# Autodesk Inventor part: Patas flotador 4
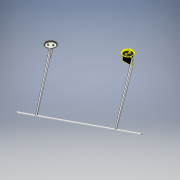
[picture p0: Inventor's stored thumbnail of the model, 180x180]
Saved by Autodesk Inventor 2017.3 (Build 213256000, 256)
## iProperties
Part Number: Patas flotador 4
Material: Plástico ABS
Document SubType Name: Modeling
Designer: PABLO HERNANDEZ
Density: 1.06 g/cm^3
Appearance: Suave - Blanco
Mass: 4.28877 g
Surface Area: 39.5254 cm^2
Volume: 4.04601 cm^3
Author: M.RICO
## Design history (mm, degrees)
sketch "Boceto1"
  geometry: C1 r 16 at (0, 0); 1 further point
  constraints: 1 centre point, 1 coincident
  dimensions: "d0" = 32 diameter of C1
extrude "Extrusión1" new body sketch "Boceto1" distance "d1" = 1; taper "d2" = 0 deg; dims "d93" = 1, "d94" = 0
sketch "Boceto2"
  geometry: C1 r 16 at (0, 0); C2 r 15 at (0, 0); C3 r 14 at (0, 0); 1 further point
  constraints: 3 centre point, 1 coincident
  dimensions: "d3" = 1 radial gap between concentric circles of C1 C2; "d4" = 1 radial gap between concentric circles of C2 C3
extrude "Extrusión2" join sketch "Boceto2" distance "d5" = 3; taper "d6" = 0 deg
sketch "Boceto3"
  geometry: C1 r 15 at (0, 0); C2 r 14 at (0, 0); 1 further point
  constraints: 2 centre point, 1 coincident
  dimensions: "d7" = 1 radial gap between concentric circles of C1 C2; "d123" = 30 diameter of C1
extrude "Extrusión3" join sketch "Boceto3" distance "d8" = 2; taper "d9" = 0 deg
sketch "Boceto4"
  geometry: C1 r 16 at (0, 0); 1 further point
  constraints: 1 centre point, 1 coincident
extrude "Extrusión4" cut sketch "Boceto4" distance "d10" = 0.5; taper "d11" = 0 deg
sketch "Boceto7"
  geometry: L1 (1.5, -15.93)-(1.5, 15.93); L2 (-1.5, -15.93)-(-1.5, 15.93); A1 r 16 centre (0, 0) between (1.5, 15.93) and (-1.5, 15.93); A2 r 16 centre (0, 0) between (-1.5, -15.93) and (1.5, -15.93); 2 further points
  constraints: 4 end point, 4 point on circle, 2 centre point, 1 coincident
extrude "Extrusión7" join sketch "Boceto7" distance "d63" = 25; taper "d64" = 0 deg
fillet "Empalme2" dims "d95" = 3
fillet "Empalme3" dims "d96" = 0.5
sketch "Boceto13"
  geometry: C1 r 1.2 at (-6, 0) reference; C2 r 1.75 at (-6, 0); C3 r 1.2 at (6, 0) reference; C4 r 1.75 at (6, 0); 1 further point
  constraints: 2 centre point, 2 coincident
  dimensions: "d118" = 3.5 diameter of C2; "d119" = 3.5 diameter of C4
extrude "Extrusión10" join sketch "Boceto13" distance "d120" = 3; taper "d121" = 0 deg
fillet "Empalme4" dims "d122" = 1
sketch "Boceto14"
  geometry: 1 further point
sketch "Boceto15"
  geometry: C1 r 1.2 at (6, 0) reference; C2 r 2.5 at (6, 0); C3 r 1.2 at (-6, 0) reference; C4 r 2.5 at (-6, 0); 1 further point
  constraints: 2 centre point, 2 coincident
  dimensions: "d124" = 5 diameter of C2; "d125" = 5 diameter of C4
extrude "Extrusión11" cut sketch "Boceto15" distance "d126" = 10; taper "d127" = 0 deg
hole "Agujero7" diameter "d151" = 2.4; stored, may be unused: countersink angle "d155" = 90 deg, drill point angle "d157" = 118 deg; dims "d149" = 10, "d150" = 10, "d152" = 6, "d153" = 4, "d154" = 2, "d156" = 8
hole "Agujero8" diameter "d160" = 2.4; stored, may be unused: countersink angle "d164" = 90 deg, drill point angle "d166" = 118 deg; dims "d158" = 10, "d159" = 10, "d161" = 6, "d162" = 4, "d163" = 2, "d165" = 8
node "Eje de trabajo1"
feature "Desplazar cuerpo1"
feature "Compuesta1"
feature "Desplazar cuerpo2"
node "Eje de trabajo2"
feature "Desplazar cuerpo3"
node "Plano de trabajo6"
sketch "Boceto27"
  geometry: L1 (0, 0)-(-149.324, -102.291); L2 (-134.431, -229.557)-(132.044, -87.232); C1 r 14 at (-149.324, -102.291) reference
  constraints: 4 end point
node "Plano de trabajo7"
node "Plano de trabajo8"
sketch "Boceto28"
  geometry: C1 r 2 at (0, 0); 1 further point
  constraints: 1 centre point
  dimensions: "d177" = 4 diameter of C1
extrude "Extrusión14" join sketch "Boceto28" stored distance "d178" = 10; taper "d179" = 0 deg
sketch "Boceto29"
  geometry: L1 (-0.28, 0)-(0, 0) reference; L2 (0, 0)-(-102.216, -91.987); L3 (-0.28, 23.165)-(-0.28, 0) reference; L4 (0, 23.165)-(0, 0) reference; L5 (0, 0)-(0, 23.165); L6 (0, 23.165)-(-105.015, -89.134); C1 r 2 at (-103.554, -90.5) reference; A1 r 2 centre (-103.554, -90.5) between (-102.216, -91.987) and (-105.015, -89.134) reference; 1 further point
  constraints: 6 end point, 2 point on circle, 2 tangent, 1 collinear
extrude "Extrusión15" join sketch "Boceto29" stored distance "d180" = 10; taper "d181" = 0 deg
node "Plano de trabajo9"
sketch "Boceto30"
  geometry: L1 (1.356, 23.165)-(1.356, 0) reference; L2 (1.356, 0)-(-130.469, -92.139); L3 (1.356, 0)-(1.356, 23.165); L4 (1.356, 23.165)-(-132.897, -88.965); A1 r 2 centre (-131.615, -90.5) between (-130.469, -92.139) and (-132.897, -88.965) reference; A2 r 2 centre (-131.615, -90.5) between (-132.897, -88.965) and (-130.469, -92.139); 1 further point
  constraints: 6 end point, 4 point on circle, 2 tangent, 1 centre point, 1 coincident, 1 vertical
extrude "Extrusión16" join sketch "Boceto30" distance "d182" = 3; taper "d183" = 0 deg
node "Sólido1"
node "Sup1"
other parameters: "sa_0" = 4, "d167" = 90 deg, "d168" = -149.324, "d169" = -102.291, "d170" = 0, "d171" = 9.86699
